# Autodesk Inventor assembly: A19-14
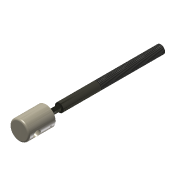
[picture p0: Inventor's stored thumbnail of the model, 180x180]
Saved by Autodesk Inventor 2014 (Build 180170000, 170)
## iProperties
Created: 2008-07
Part Number: A19-14
Document SubType Name: Assembly
Designer: y-shimohigashi
Stock Number: A19-14
Author: y-shimohigashi
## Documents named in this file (3)
- \\SVFL01\Data\技術\CAD\Inventor\テキスト\Inventor_教育Text\R2014（仮）\Inventor2014基礎コース\練習問題-19\A19-14.iam
- \\SVFL01\Data\技術\CAD\Inventor\テキスト\Inventor_教育Text\R2014（仮）\Inventor2014基礎コース\練習問題-19\P19-5締付ネジ.ipt
- \\SVFL01\Data\技術\CAD\Inventor\テキスト\Inventor_教育Text\R2014（仮）\Inventor2014基礎コース\練習問題-19\P19-7ハンドル取付棒.ipt
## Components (2 placed, 2 different names)
1. P19-5締付ネジ:1
2. P19-7ハンドル取付棒:1
